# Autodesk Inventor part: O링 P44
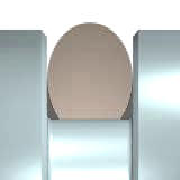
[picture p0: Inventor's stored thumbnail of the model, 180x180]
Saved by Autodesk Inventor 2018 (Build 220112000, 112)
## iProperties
Created: 2012-02
Part Number: O링 P44
Material: 고무
Description: O-링
Document SubType Name: Modeling
Standard: JIS 2406
Designer: mdu-01
Standards Organization: JIS
Language: ko-KR
Size Designation: P44
Categories: <MemberInstance><Categories><Category DisplayName="샤프트 부품" InternalName="7f7aeb1f-a693-4053-b835-cee3144e0d98" Mnemonic="SHFT"><Category DisplayName="실링" Intern
Density: 0.93 g/cm^3
Appearance: 고무 - 검은색 - 버전 1.1
IsCustomPart: 1
Author: mdu-01
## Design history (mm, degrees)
revolve "본체" stored, may be unused: angle "d19" = 90 deg
body "Solid1"
sketch "스케치1"
  geometry: L1 (-0.901, 0)-(0.901, 0); L2 (-2.412, 0)-(3.006, 0) reference; L3 (0.901, -3)-(-0.901, -3); L4 (-1.638, -25)-(2.232, -25); L5 (0, 1.8)-(0, -10.8) reference; L6 (0, 0)-(0, 0); A1 r 1.75 centre (0, -1.5) between (-0.901, 0) and (-0.901, -3); A2 r 1.75 centre (0, -1.5) between (0.901, -3) and (0.901, 0)
  constraints: 8 end point, 4 point on circle, 4 point on line, 2 centre point, 2 parallel, 1 coincident, 1 horizontal, 1 horizontal alignment, 1 vertical alignment, 1 other
  dimensions: "d0" = 44 diameter of L3 L4 (= NDOR); "d1" = 1.5 distance from line of L3 A1.centre (= -0.25 x NDOR + 0.25 x NND); "d2" = 50 diameter of L2 L4 (= NND); "d3" = 1.75 radius of A1 (= 0.5 x QDM)
other parameters: "QDM" = 3.5 [user parameter; used in 1 equation term], "NND" = 50 [user parameter; used in 3 equation terms], "NDOR" = 44 [user parameter; used in 3 equation terms], "d4" = 0, "d26" = 0, "R2" = 0.2 [user parameter], "SD1" = 43.7 [user parameter], "R1" = 0.7 [user parameter], "NB2" = 6 [user parameter], "NB1" = 4.7 [user parameter], "NB3" = 7.8 [user parameter], "BD" = 49.85 [user parameter], "NTOR" = 3 (= -0.5 x NDOR + 0.5 x NND) [user parameter]
